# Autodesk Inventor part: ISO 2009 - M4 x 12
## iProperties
Created: 2002-11
Part Number: ISO 2009 - M4 x 12
Material: Standard
Catalog Web Link: file:///C:/Programme/Autodesk/Inventor%205.3/Content/Din/index.htm?doNavigateId=05B843F3-BF7B-11D4-A9EA-0080AD303E0A|0557D0EEB16611D4BA6900C04F798F98|true
Description: Senkschraube
Document SubType Name: Standard Catalog Part
Standard: ISO 2009 - M4 x 12
Designer: Administrator
Control State: 0
Master: False
Checked Out: False
Shininess: 20.0
Angle Display Precision: 2
Document Length Units: 11269
Document Angle Units: 11279
Document Time Units: 11290
Document Mass Units: 11283
Document Length Units Precision: 3
Document Angle Units Precision: 2
Compacted: True
KLASSIFIKATION: 31161513 un/spsc
HERSTELLER: DIN Normsystem
Density: 0.0
Volumn: 0.0
Area: 0.0
PropertySet Name: Model Information
Author: Administrator
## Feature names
1. Basis1
